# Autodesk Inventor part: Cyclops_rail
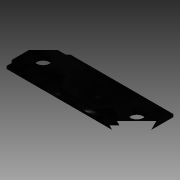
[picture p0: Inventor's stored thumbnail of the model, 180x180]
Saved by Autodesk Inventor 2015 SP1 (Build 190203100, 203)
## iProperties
Created: 2015-04
Part Number: Cyclops_rail
Material: Generic
Document SubType Name: Modeling
Designer: salte_000
Density: 1 g/cm^3
Appearance: Default
Author: salte_000
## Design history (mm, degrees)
sketch "Sketch1"
  geometry: L1 (-24, 8)-(24, 8); L2 (24, 8)-(24, -8); L3 (24, -8)-(-24, -8); L4 (-24, -8)-(-24, 8); C1 r 2.5 at (-18, 0); C2 r 2.5 at (18, 0); 3 further points
  constraints: 8 end point, 3 horizontal alignment, 2 centre point, 2 midpoint, 2 parallel, 1 horizontal, 1 perpendicular, 1 vertical alignment
  dimensions: "d0" = 16 distance between parallel lines of L3 L1; "d1" = 5 diameter of C1; "d2" = 5 diameter of C2; "d11" = 6 distance from line of L4 C1.centre; "d12" = 36 distance of C2.centre C1.centre; "d13" = 6 distance from line of L2 C2.centre
extrude "Extrusion1" new body sketch "Sketch1" distance "d6" = 1; taper "d7" = 0 deg
sketch "Sketch2"
  geometry: L1 (-24, 8)-(-24, -8) reference; L2 (24, -8)-(24, 8) reference; L3 (-24, 6.1)-(24, 6.1); L4 (24, 6.1)-(24, -6.1); L5 (24, -6.1)-(-24, -6.1); L6 (-24, -6.1)-(-24, 6.1); C1 r 2.5 at (18, 0) reference; C2 r 2.5 at (-18, 0) reference; 2 further points
  constraints: 8 end point, 2 parallel, 2 point on line, 1 horizontal, 1 horizontal alignment, 1 midpoint, 1 perpendicular
  dimensions: "d8" = 12.2 distance between parallel lines of L5 L3
extrude "Extrusion2" join sketch "Sketch2" distance "d9" = 1; taper "d10" = 0 deg
body "Solid1"
